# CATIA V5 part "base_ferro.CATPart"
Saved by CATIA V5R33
Part number: base_ferro
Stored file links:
  C:\Users\Ryzen5700u\Desktop\robot_cicloidale_singolo\Assieme_robot_cicloidale_singolo\base_ferro.CATPart

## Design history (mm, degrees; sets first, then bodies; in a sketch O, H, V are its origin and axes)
Body1 "Solido1" (main body)
  Solid1: solid without history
